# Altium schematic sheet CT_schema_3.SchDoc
size 479 x 328 mm
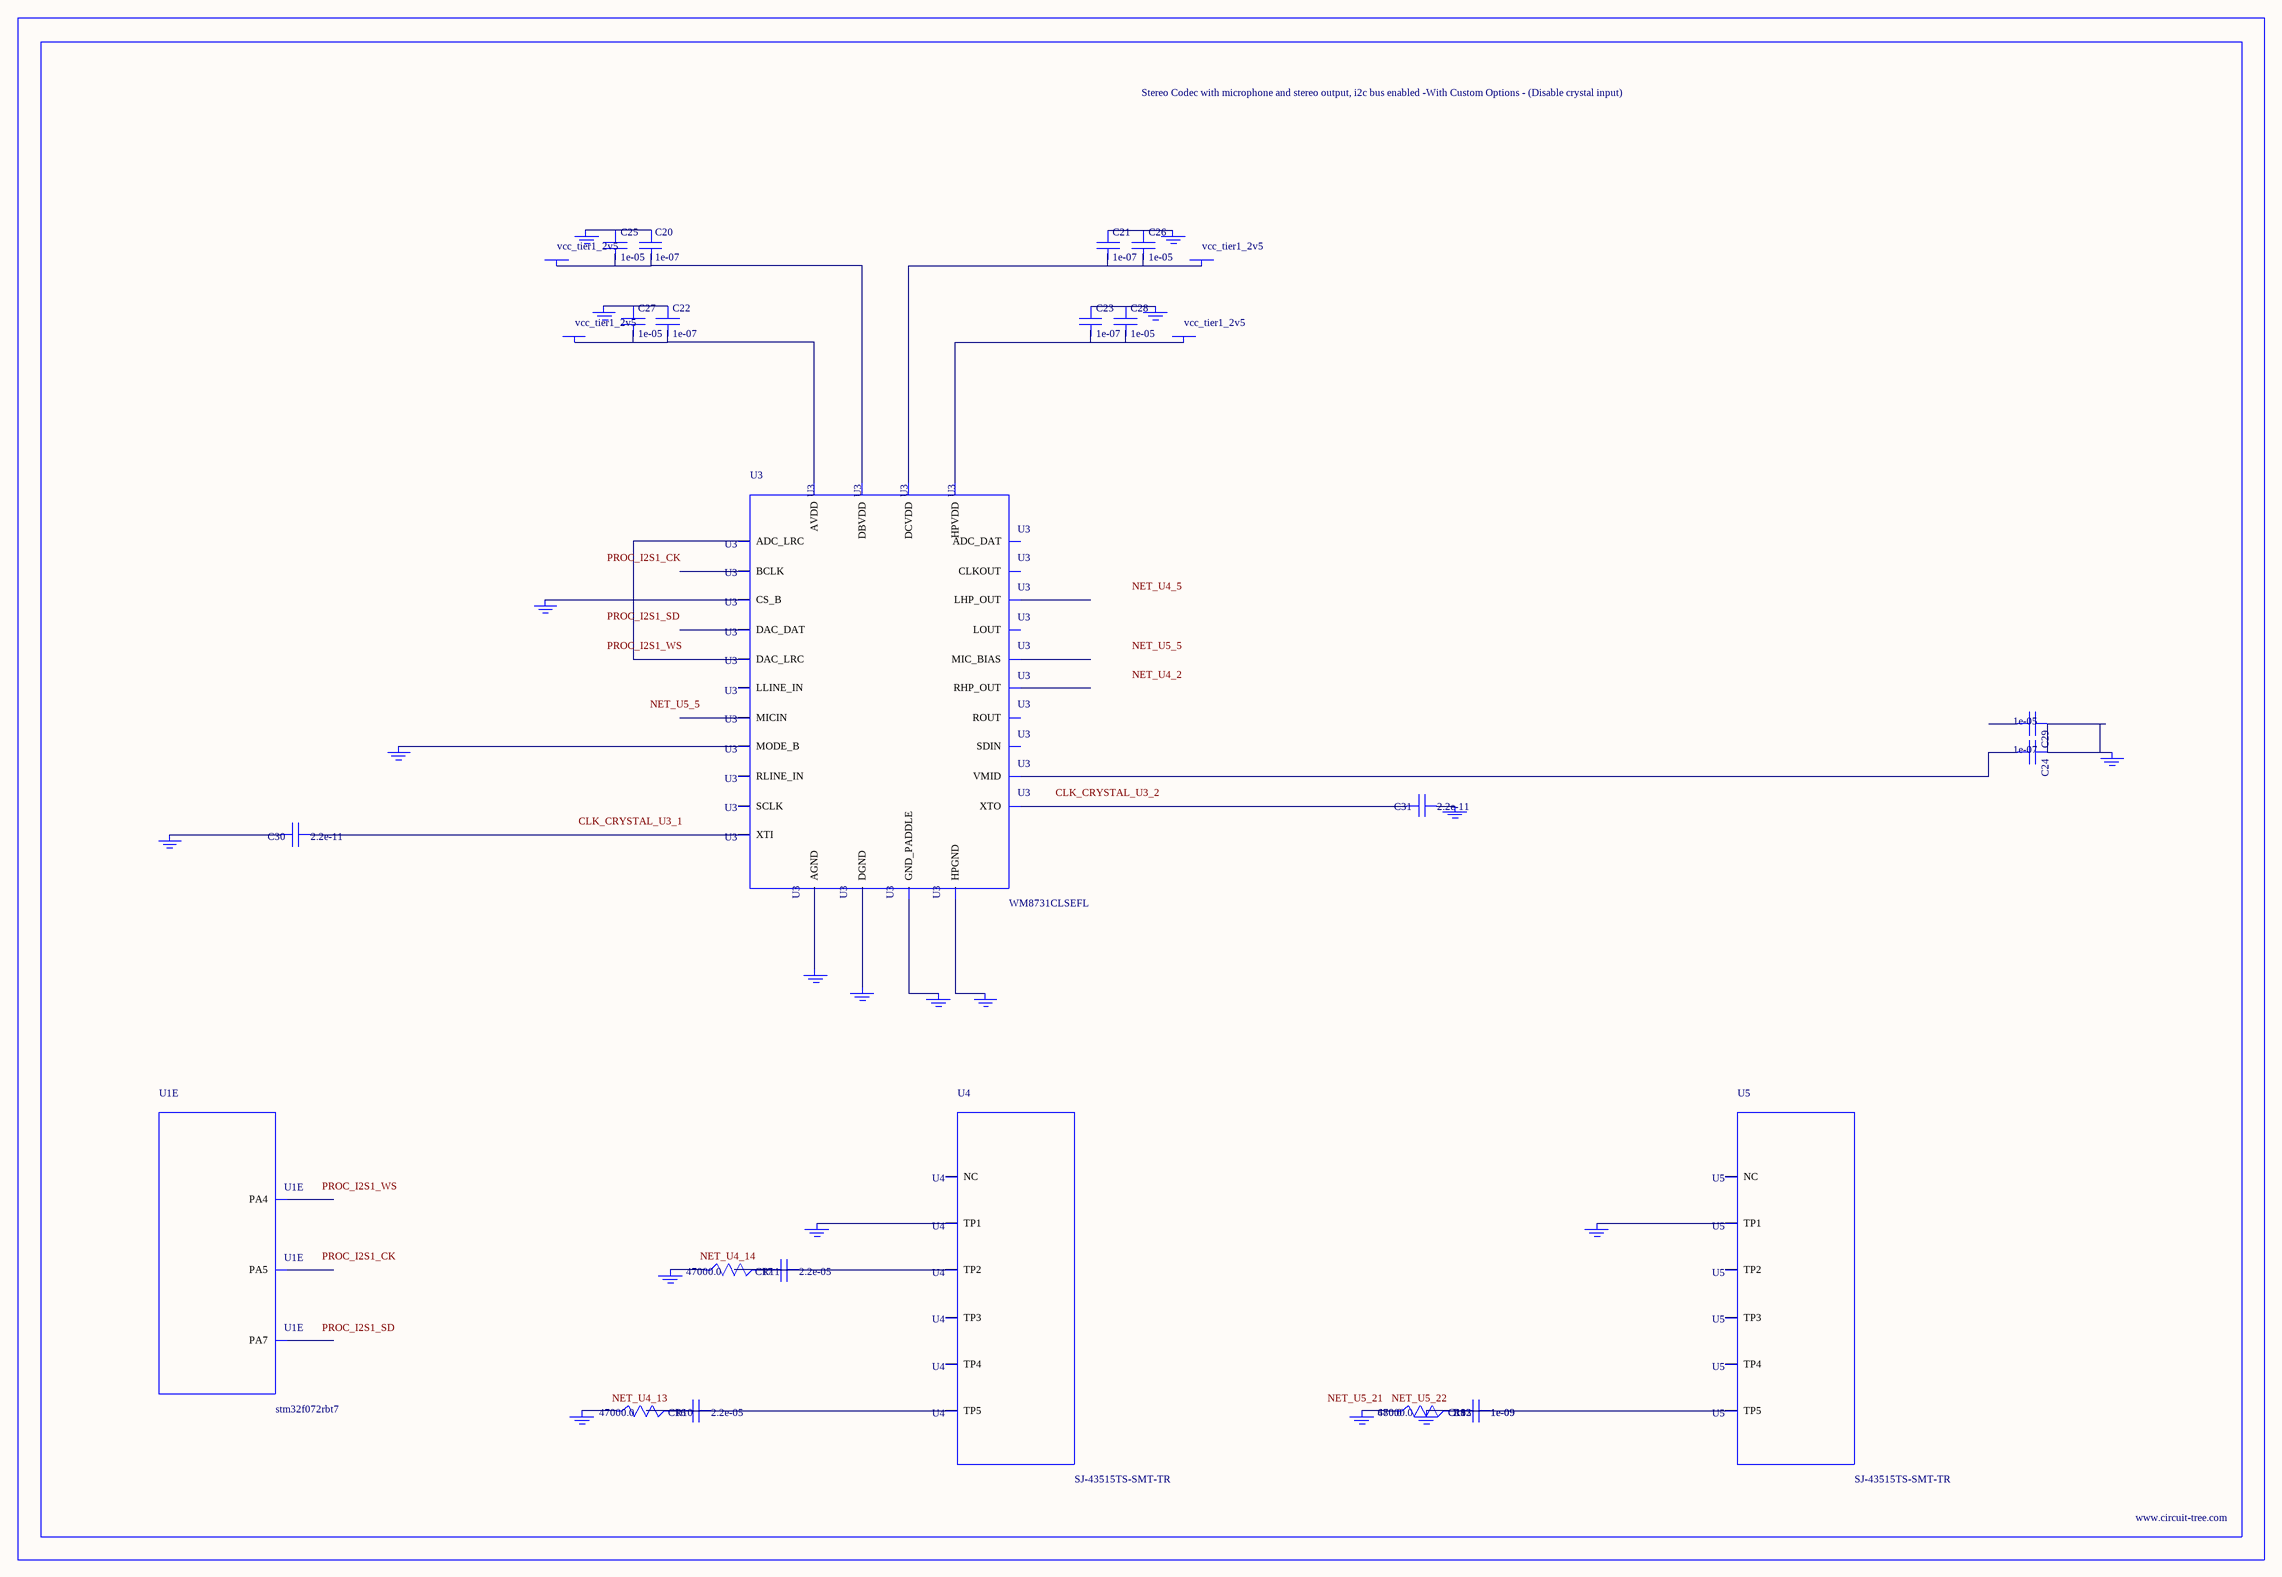
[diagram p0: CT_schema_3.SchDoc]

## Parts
BORDER2  (no value)
C16  2.2e-05  [C1210]
C17  2.2e-05  [C1210]
C18  1e-09  [C0402]
C19  1e-09  [C0402]
C20  1e-07  [C0402]
C21  1e-07  [C0402]
C22  1e-07  [C0402]
C23  1e-07  [C0402]
C24  1e-07  [C0402]
C25  1e-05  [C0805]
C26  1e-05  [C0805]
C27  1e-05  [C0805]
C28  1e-05  [C0805]
C29  1e-05  [C0805]
C30  2.2e-11  [C0402]
C31  2.2e-11  [C0402]
GND_INSTANCE_2_0  (no value)
GND_INSTANCE_2_1  (no value)
GND_INSTANCE_2_2  (no value)
GND_INSTANCE_2_3  (no value)
GND_INSTANCE_2_4  (no value)
GND_INSTANCE_2_5  (no value)
GND_INSTANCE_2_6  (no value)
GND_INSTANCE_2_7  (no value)
GND_INSTANCE_2_8  (no value)
GND_INSTANCE_2_9  (no value)
GND_INSTANCE_2_10  (no value)
GND_INSTANCE_2_11  (no value)
GND_INSTANCE_2_12  (no value)
GND_INSTANCE_2_13  (no value)
GND_INSTANCE_2_14  (no value)
GND_INSTANCE_2_15  (no value)
GND_INSTANCE_2_16  (no value)
GND_INSTANCE_2_17  (no value)
GND_INSTANCE_2_18  (no value)
POWER_INSTANCE_2_0  vcc_tier1_2v5
POWER_INSTANCE_2_1  vcc_tier1_2v5
POWER_INSTANCE_2_2  vcc_tier1_2v5
POWER_INSTANCE_2_3  vcc_tier1_2v5
R10  47000.0  [R0603]
R11  47000.0  [R0603]
R12  47000.0  [R0603]
R13  680.0  [R0603]
U1  stm32f072rbt7  [LQFP64]  (part E of 6)
U3  WM8731CLSEFL  [QFN-28]
U4  SJ-43515TS-SMT-TR  [SJ-43515TS-SMT-TR]
U5  SJ-43515TS-SMT-TR  [SJ-43515TS-SMT-TR]

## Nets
NetC16_1: C16.1 C16.2 R10.2 U4.5(TP5)
NetC17_1: C17.1 C17.2 R11.2 U4.2(TP2)
NetC18_1: C18.1 C18.2 C19.1 C19.2 GND_INSTANCE_2_18.0(GND) R12.2 R13.2 U5.5(TP5)
NetC20_1: C20.1 C25.1 GND_INSTANCE_2_3.0(GND)
NetC20_2: C20.2 C25.2 POWER_INSTANCE_2_1.0(PWR) U3.5(DBVDD)
NetC21_1: C21.1 C26.1 GND_INSTANCE_2_2.0(GND)
NetC21_2: C21.2 C26.2 POWER_INSTANCE_2_0.0(PWR) U3.3(DCVDD)
NetC22_1: C22.1 C27.1 GND_INSTANCE_2_6.0(GND)
NetC22_2: C22.2 C27.2 POWER_INSTANCE_2_3.0(PWR) U3.18(AVDD)
NetC23_1: C23.1 C28.1 GND_INSTANCE_2_4.0(GND)
NetC23_2: C23.2 C28.2 POWER_INSTANCE_2_2.0(PWR) U3.12(HPVDD)
NetC24_1: C24.1 C29.1 GND_INSTANCE_2_7.0(GND)
NetC24_2: C24.2 U3.20(VMID)
NetC30_1: C30.1 U3.1(XTI)
NetC30_2: C30.2 GND_INSTANCE_2_0.0(GND)
NetC31_1: C31.1 GND_INSTANCE_2_1.0(GND)
NetC31_2: C31.2 U3.2(XTO)
NetGND_INSTANCE_2_5_0: GND_INSTANCE_2_5.0(GND) U3.15(HPGND)
NetGND_INSTANCE_2_8_0: GND_INSTANCE_2_8.0(GND) U3.25(MODE_B)
NetGND_INSTANCE_2_9_0: GND_INSTANCE_2_9.0(GND) U3.26(CS_B)
NetGND_INSTANCE_2_10_0: GND_INSTANCE_2_10.0(GND) U3.29(GND_PADDLE)
NetGND_INSTANCE_2_11_0: GND_INSTANCE_2_11.0(GND) U3.4(DGND)
NetGND_INSTANCE_2_12_0: GND_INSTANCE_2_12.0(GND) U3.19(AGND)
NetGND_INSTANCE_2_13_0: GND_INSTANCE_2_13.0(GND) U4.1(TP1)
NetGND_INSTANCE_2_14_0: GND_INSTANCE_2_14.0(GND) R11.1
NetGND_INSTANCE_2_15_0: GND_INSTANCE_2_15.0(GND) R10.1
NetGND_INSTANCE_2_16_0: GND_INSTANCE_2_16.0(GND) U5.1(TP1)
NetGND_INSTANCE_2_17_0: GND_INSTANCE_2_17.0(GND) R12.1 R13.1
NetU3_9: U3.9(DAC_LRC) U3.11(ADC_LRC)

Not connected (* = marked no-connect by the designer): C29 2; U1 20(PA4) 21(PA5) 23(PA7); U3 6(CLKOUT) 7(BCLK) 8(DAC_DAT) 10(ADC_DAT) 13(LHP_OUT) 14(RHP_OUT) 16(LOUT) 17(ROUT) 21(MIC_BIAS) 22(MICIN) 23(RLINE_IN) 24(LLINE_IN) 27(SDIN) 28(SCLK); U4 3(TP3) 4(TP4) 6(NC); U5 2(TP2) 3(TP3) 4(TP4) 6(NC)

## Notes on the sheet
- Labels drawn without touching a wire or pin: CLK_CRYSTAL_U3_1, CLK_CRYSTAL_U3_2, NET_U4_2, NET_U4_5, NET_U4_13, NET_U4_14, NET_U5_5, NET_U5_21, NET_U5_22, PROC_I2S1_CK, PROC_I2S1_SD, PROC_I2S1_WS

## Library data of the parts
BORDER2 = BORDER_PAGE2
C16 C17 = C1210C224K5RACTU
C18 C19 = C0402C102K3RAC
C20-C24 = C0402C104K3RACTU
C25-C29 = C0805C106K8RACTU
C30 C31 = C0402C220K3RAC
GND_INSTANCE_2_0-GND_INSTANCE_2_18 = GND
POWER_INSTANCE_2_0-POWER_INSTANCE_2_3 = PWR
R10-R12 = RC0603JR-0747KL
R13 = RC0603JR-07680RL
